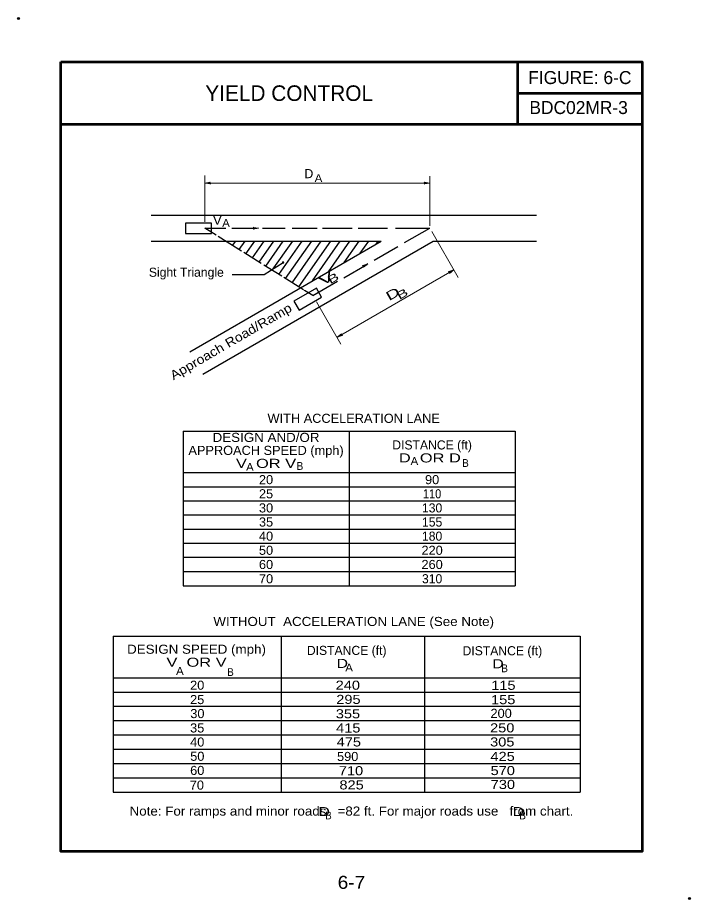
# Model space of a CAD drawing. Extents: x -3.354 to -2.679, y 3.051 to 3.935.
import ezdxf
from ezdxf.enums import TextEntityAlignment as Align

# ---------------------------------------------------------------- set-up
doc = ezdxf.new("R2010")
doc.units = 0
doc.header["$LTSCALE"] = 0.0036
doc.header["$PDMODE"] = 32
doc.header["$PDSIZE"] = 0.0018
doc.layers.add('1', color=7, linetype='Continuous', lineweight=25)
doc.layers.add('2', color=7, linetype='Continuous', lineweight=25)

msp = doc.modelspace()

# ---------------------------------------------------------------- linework, layer by layer
at = {"layer": '1', "lineweight": 53}
for p, q in [((-2.852792, 3.890983), (-2.852792, 3.828483)), ((-2.852792, 3.859733), (-2.727792, 3.859733)), ((-3.311125, 3.828483), (-2.727792, 3.828483))]:
    msp.add_line(p, q, dxfattribs=at)
at = {"layer": '1', "lineweight": 13}
for p, q in [((-3.166642, 3.730783), (-3.166642, 3.777025)), ((-2.940925, 3.726683), (-2.940925, 3.776592)), ((-3.166642, 3.769558), (-2.940925, 3.769558)), ((-2.938933, 3.720925), (-2.912292, 3.674767)), ((-3.03405, 3.6148), (-2.916758, 3.682517)), ((-3.054575, 3.65035), (-3.030133, 3.608008))]:
    msp.add_line(p, q, dxfattribs=at)
at = {"layer": '1'}
for p, q in [((-3.166575, 3.769533), (-3.161217, 3.770325)), ((-2.940975, 3.769567), (-2.946333, 3.768775)), ((-3.220375, 3.7374), (-2.833667, 3.7374)), ((-3.166642, 3.724383), (-3.145633, 3.724383)), ((-3.139492, 3.724383), (-3.115342, 3.724383)), ((-3.112675, 3.724242), (-3.118033, 3.72345)), ((-3.10875, 3.724383), (-3.085925, 3.724383)), ((-3.078908, 3.724383), (-3.053792, 3.724383)), ((-3.048617, 3.724383), (-3.018758, 3.724383)), ((-3.012617, 3.724383), (-2.9832, 3.724383)), ((-2.975292, 3.724383), (-2.940925, 3.724383)), ((-2.966083, 3.709858), (-2.940925, 3.724383)), ((-3.220375, 3.711358), (-2.989542, 3.711358)), ((-3.181742, 3.600392), (-2.989542, 3.711358)), ((-3.168708, 3.577825), (-2.937433, 3.711358)), ((-2.9966, 3.692233), (-2.972975, 3.705883)), ((-2.937433, 3.711358), (-2.833667, 3.711358)), ((-3.027117, 3.674617), (-3.004158, 3.687883)), ((-3.003058, 3.688425), (-3.0073, 3.685067)), ((-2.916892, 3.682367), (-2.921133, 3.679017)), ((-3.058217, 3.656658), (-3.033383, 3.671008)), ((-3.033758, 3.61505), (-3.029517, 3.618408)), ((-3.188517, 3.520867), (-2.855183, 3.520867)), ((-3.188517, 3.520867), (-3.188517, 3.365558)), ((-3.02185, 3.520867), (-3.02185, 3.365558)), ((-2.855183, 3.520867), (-2.855183, 3.365558)), ((-3.188517, 3.4792), (-2.855183, 3.4792)), ((-3.188517, 3.465033), (-2.855183, 3.465033)), ((-3.188517, 3.450867), (-2.855183, 3.450867)), ((-3.188517, 3.4367), (-2.855183, 3.4367)), ((-3.188517, 3.422533), (-2.855183, 3.422533)), ((-3.188517, 3.408367), (-2.855183, 3.408367)), ((-3.188517, 3.3942), (-2.855183, 3.3942)), ((-3.188517, 3.379883), (-2.855183, 3.379883)), ((-3.188517, 3.365558), (-2.855183, 3.365558)), ((-3.258633, 3.315083), (-2.789883, 3.315083)), ((-3.258633, 3.315083), (-3.258633, 3.158833)), ((-3.089908, 3.315083), (-3.089908, 3.158833)), ((-2.946133, 3.315083), (-2.946133, 3.158833)), ((-2.789883, 3.315083), (-2.789883, 3.158833)), ((-3.258633, 3.273417), (-2.789883, 3.273417)), ((-3.258633, 3.2591), (-2.789883, 3.2591)), ((-3.258633, 3.244775), (-2.789883, 3.244775)), ((-3.258633, 3.23045), (-2.789883, 3.23045)), ((-3.258633, 3.216125), (-2.789883, 3.216125)), ((-3.258633, 3.201808), (-2.789883, 3.201808)), ((-3.258633, 3.187483), (-2.789883, 3.187483)), ((-3.258633, 3.173158), (-2.789883, 3.173158)), ((-3.258633, 3.158833), (-2.789883, 3.158833))]:
    msp.add_line(p, q, dxfattribs=at)
at = {"layer": '1', "lineweight": 53}
msp.add_lwpolyline([(-3.311125, 3.890983), (-2.727792, 3.890983), (-2.727792, 3.099317), (-3.311125, 3.099317)], close=True, dxfattribs=at)
at = {"layer": '1'}
for points in [[(-3.162125, 3.76955), (-3.161083, 3.768683), (-3.166633, 3.76955)], [(-3.161208, 3.770308), (-3.162125, 3.769567), (-3.162125, 3.76955)], [(-2.945425, 3.769558), (-2.946467, 3.770417), (-2.940917, 3.769542)], [(-2.946342, 3.768792), (-2.945425, 3.769542), (-2.945425, 3.769558)], [(-3.117125, 3.724233), (-3.118167, 3.7251), (-3.112617, 3.724233)], [(-3.118042, 3.723475), (-3.117125, 3.724217), (-3.117125, 3.724233)], [(-3.139308, 3.677842), (-3.107042, 3.677842), (-3.088008, 3.689908)], [(-3.006908, 3.686192), (-3.008242, 3.686425), (-3.003, 3.688442)], [(-3.007325, 3.685075), (-3.006892, 3.686175), (-3.006908, 3.686192)], [(-2.920742, 3.680142), (-2.922075, 3.680367), (-2.916833, 3.682392)], [(-2.921158, 3.679025), (-2.920725, 3.680117), (-2.920742, 3.680142)], [(-3.029917, 3.617283), (-3.028583, 3.617058), (-3.033825, 3.615025)], [(-3.0295, 3.6184), (-3.029925, 3.617308), (-3.029917, 3.617283)]]:
    msp.add_lwpolyline(points, dxfattribs=at)
for points in [[(-3.186058, 3.729283), (-3.186058, 3.718867), (-3.160017, 3.718867), (-3.160017, 3.729283)], [(-3.077217, 3.651175), (-3.072008, 3.64215), (-3.049458, 3.655175), (-3.054667, 3.664192)]]:
    msp.add_lwpolyline(points, close=True, dxfattribs=at)
at = {"layer": '1', "lineweight": 35}
msp.add_circle((-3.088008, 3.68991), 0.000522, dxfattribs=at)
at = {"layer": '1'}
for p in [(-3.353583, 3.934567), (-2.68025, 3.052067)]:
    msp.add_point(p, dxfattribs=at)
at = {"layer": '2'}
for p, q in [((-3.155092, 3.717175), (-3.166642, 3.724383)), ((-3.129875, 3.701408), (-3.153242, 3.716008)), ((-3.145367, 3.711092), (-3.145175, 3.711358)), ((-3.138725, 3.706942), (-3.135633, 3.711358)), ((-3.132092, 3.702808), (-3.1261, 3.711358)), ((-3.125458, 3.698658), (-3.116558, 3.711358)), ((-3.118825, 3.694517), (-3.107033, 3.711358)), ((-3.112183, 3.690367), (-3.097492, 3.711358)), ((-3.10555, 3.686225), (-3.08795, 3.711358)), ((-3.098917, 3.682075), (-3.078417, 3.711358)), ((-3.092283, 3.677933), (-3.068875, 3.711358)), ((-3.085642, 3.6738), (-3.059342, 3.711358)), ((-3.079008, 3.66965), (-3.0498, 3.711358)), ((-3.072375, 3.665508), (-3.040258, 3.711358)), ((-3.058675, 3.67145), (-3.030725, 3.711358)), ((-3.042667, 3.680692), (-3.021183, 3.711358)), ((-3.026658, 3.689933), (-3.011658, 3.711358)), ((-3.010642, 3.699175), (-3.002117, 3.711358)), ((-2.994633, 3.708425), (-2.992583, 3.711358)), ((-3.10995, 3.688967), (-3.127508, 3.699933)), ((-3.089375, 3.676117), (-3.107375, 3.687358)), ((-3.067467, 3.662442), (-3.0872, 3.674767))]:
    msp.add_line(p, q, dxfattribs=at)
msp.add_lwpolyline([(-3.058217, 3.656658), (-3.066633, 3.661925), (-3.066758, 3.661992)], dxfattribs=at)

# ---------------------------------------------------------------- texts
at = {"layer": '1'}
for s, height, p in [('FIGURE: 6-C', 0.01303, (-2.790292, 3.868842)), ('YIELD CONTROL', 0.01562, (-3.081958, 3.851917)), ('BDC02MR-3', 0.01303, (-2.791496, 3.838792)), ('D', 0.009117, (-3.062196, 3.774467)), ('Sight Triangle', 0.009117, (-3.185175, 3.675592)), ('DISTANCE (ft)', 0.009117, (-2.938517, 3.502383)), ('130', 0.009117, (-2.938521, 3.439217)), ('155', 0.009117, (-2.938517, 3.42505)), ('180', 0.009117, (-2.938521, 3.410883)), ('310', 0.009117, (-2.938521, 3.368158)), ('DISTANCE (ft)', 0.009117, (-3.024258, 3.2963)), ('DISTANCE (ft)', 0.009117, (-2.868008, 3.29595))]:
    msp.add_text(s, height=height, dxfattribs=at).set_placement(p, align=Align.CENTER)
at = {"layer": '1', "width": 1.1}
for p in [(-3.056383, 3.77065), (-3.1492, 3.725558)]:
    msp.add_text('A', height=0.007817, dxfattribs=at).set_placement(p)
at = {"layer": '1'}
for s, height, width, p in [('V', 0.009117, 1.1, (-3.154033, 3.727833)), ('WITH ACCELERATION LANE', 0.009117, 1.05, (-3.017238, 3.529067)), ('DESIGN AND/OR', 0.009117, 1.1, (-3.105183, 3.509925)), ('APPROACH SPEED (mph)', 0.009117, 1.05, (-3.105183, 3.4969)), ('V  OR V', 0.009117, 1.35, (-3.105183, 3.483875)), ('D  OR D ', 0.009117, 1.35, (-2.938517, 3.489358)), ('A', 0.007817, 1.1, (-2.956292, 3.486867)), ('A', 0.007817, 1.1, (-3.1214, 3.48095)), ('B', 0.007817, 0.95, (-3.071133, 3.481917)), ('B', 0.007817, 0.95, (-2.90505, 3.484875)), ('20', 0.009117, 1.05, (-3.105183, 3.46755)), ('90', 0.009117, 1.05, (-2.938517, 3.46755)), ('25', 0.009117, 1.05, (-3.105187, 3.453383)), ('110', 0.009117, 0.9, (-2.938521, 3.453383)), ('30', 0.009117, 1.05, (-3.105183, 3.439217)), ('35', 0.009117, 1.05, (-3.105187, 3.42505)), ('40', 0.009117, 1.05, (-3.105183, 3.410883)), ('50', 0.009117, 1.05, (-3.105183, 3.396717)), ('220', 0.009117, 1.05, (-2.938521, 3.396717)), ('60', 0.009117, 1.05, (-3.105183, 3.382475)), ('260', 0.009117, 1.05, (-2.938521, 3.382475)), ('70', 0.009117, 1.05, (-3.105183, 3.368158)), ('WITHOUT  ACCELERATION LANE (See Note)', 0.009117, 1.1, (-3.017238, 3.325325)), ('DESIGN SPEED (mph)', 0.009117, 1.1, (-3.174937, 3.297492)), ('V  OR V', 0.009117, 1.35, (-3.174933, 3.284467)), ('D  ', 0.009117, 1.3, (-3.024258, 3.283275)), ('D  ', 0.009117, 1.3, (-2.868008, 3.282925)), ('A', 0.007817, 1.1, (-3.191625, 3.276325)), ('B', 0.007817, 0.95, (-3.140875, 3.275217)), ('A', 0.007817, 1.1, (-3.021842, 3.279742)), ('B', 0.007817, 0.95, (-2.865792, 3.278967)), ('20', 0.009117, 1.05, (-3.174275, 3.261392)), ('240', 0.009117, 1.2, (-3.023108, 3.261417)), ('115', 0.009117, 1.2, (-2.867008, 3.261292)), ('25', 0.009117, 1.05, (-3.174279, 3.247)), ('295', 0.009117, 1.2, (-3.0225, 3.247175)), ('155', 0.009117, 1.2, (-2.867167, 3.2469)), ('30', 0.009117, 1.05, (-3.174083, 3.23295)), ('355', 0.009117, 1.2, (-3.022983, 3.232733)), ('200', 0.009117, 1.05, (-2.869246, 3.233167)), ('35', 0.009117, 1.05, (-3.174279, 3.218533)), ('250', 0.009117, 1.2, (-2.868167, 3.218633)), ('415', 0.009117, 1.2, (-3.02265, 3.218508)), ('40', 0.009117, 1.05, (-3.174233, 3.204433)), ('475', 0.009117, 1.2, (-3.022092, 3.204508)), ('305', 0.009117, 1.2, (-2.868125, 3.204508)), ('50', 0.009117, 1.05, (-3.174175, 3.190133)), ('590', 0.009117, 1.05, (-3.023254, 3.189917)), ('425', 0.009117, 1.2, (-2.867767, 3.189992)), ('60', 0.009117, 1.05, (-3.174217, 3.175908)), ('710', 0.009117, 1.2, (-3.01995, 3.175633)), ('570', 0.009117, 1.2, (-2.867617, 3.175817)), ('70', 0.009117, 1.05, (-3.174625, 3.161217)), ('825', 0.009117, 1.2, (-3.019308, 3.161408)), ('730', 0.009117, 1.2, (-2.867517, 3.161858)), ('Note: For ramps and minor roads   =82 ft. For major roads use   from chart.', 0.009117, 1.1, (-3.019462, 3.135175)), ('D  ', 0.009117, 1.3, (-3.042508, 3.134633)), ('D  ', 0.009117, 1.3, (-2.847592, 3.134633)), ('D  ', 0.009117, 1.3, (-2.847592, 3.134633)), ('B', 0.007817, 0.95, (-3.042583, 3.131417)), ('B', 0.007817, 0.95, (-2.847667, 3.131417)), ('B', 0.007817, 0.95, (-2.847667, 3.131417)), ('6-7', 0.01303, 1.1, (-3.019458, 3.061733))]:
    msp.add_text(s, height=height, dxfattribs=dict(at, width=width)).set_placement(p, align=Align.CENTER)
for s, height, width, p in [('V', 0.009117, 1.75, (-3.048625, 3.666175)), ('B', 0.007817, 1.6, (-3.040775, 3.667992)), ('D', 0.009117, 1.55, (-2.981667, 3.651075)), ('B', 0.007817, 1.6, (-2.971375, 3.652258))]:
    msp.add_text(s, height=height, rotation=30, dxfattribs=dict(at, width=width)).set_placement(p)
at = {"layer": '1', "width": 1.15}
msp.add_text('Approach Road/Ramp', height=0.009117, rotation=30.277, dxfattribs=at).set_placement((-3.138169, 3.606743), align=Align.CENTER)

doc.saveas('drawing.dxf')
